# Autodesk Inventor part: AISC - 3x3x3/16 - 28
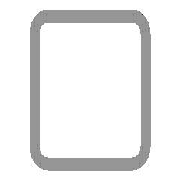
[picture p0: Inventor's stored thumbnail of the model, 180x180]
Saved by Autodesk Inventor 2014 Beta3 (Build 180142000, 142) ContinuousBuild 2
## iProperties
_CCFamilyMember: 9
_CCFamilyDisplayName: ANSI AISC (Square) - Tube
_FrameMemberDoc: Frame Member File
_Version: 15.0.0
_GetPNFromCC: 1
Created: 2010-11
Part Number: AISC - 3x3x3/16 - 28
Material: Steel, Mild
Description: Tube
Document SubType Name: Modeling
Standard: ANSI
Designer: Beta-8540w
Standards Organization: ANSI
Language: en-US
Size Designation: 3x3x3/16
Categories: <MemberInstance><Categories><Category DisplayName="Structural Shapes" InternalName="089c4875-fa83-4c05-b084-43b9cc11f5ed" Mnemonic="GRDR"><CategoryParameter Dis
Stock Number: 3x3x3/16
Density: 7.86 g/cm^3
Appearance: Steel
IsCustomPart: 1
G_L: 28.000 in
G_W: 3.000 in
G_H: 3.000 in
Author: Beta-8540w
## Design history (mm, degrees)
node "Start plane"
node "End plane"
sketch "Sketch"
  geometry: L1 (-38.1, -28.575)-(-38.1, 28.575); L2 (-28.575, 38.1)-(28.575, 38.1); L3 (38.1, 28.575)-(38.1, -28.575); L4 (28.575, -38.1)-(-28.575, -38.1); L5 (-28.575, 33.337)-(28.575, 33.338); L6 (33.338, 28.575)-(33.338, -28.575); L7 (28.575, -33.337)-(-28.575, -33.338); L8 (-33.338, -28.575)-(-33.338, 28.575); L9 (0, 56.102)-(0, -56.102) reference; L10 (-56.102, 0)-(56.102, 0) reference; A1 r 9.525 centre (-28.575, -28.575) between (-38.1, -28.575) and (-28.575, -38.1); A2 r 9.525 centre (-28.575, 28.575) between (-28.575, 38.1) and (-38.1, 28.575); A3 r 9.525 centre (28.575, 28.575) between (38.1, 28.575) and (28.575, 38.1); A4 r 9.525 centre (28.575, -28.575) between (28.575, -38.1) and (38.1, -28.575); A5 r 4.763 centre (-28.575, 28.575) between (-28.575, 33.337) and (-33.338, 28.575); A6 r 4.763 centre (28.575, 28.575) between (33.338, 28.575) and (28.575, 33.338); A7 r 4.763 centre (28.575, -28.575) between (28.575, -33.337) and (33.338, -28.575); A8 r 4.763 centre (-28.575, -28.575) between (-33.338, -28.575) and (-28.575, -33.338)
  constraints: 16 end point, 16 point on circle, 8 centre point, 8 tangent, 4 parallel, 3 equal radius, 2 perpendicular, 7 other
  dimensions: "d10" = 76.2 distance between parallel lines of L2 L4 (= G_H); "d11" = 76.2 distance between parallel lines of L1 L3 (= G_W); "d12" = 4.7625 distance between parallel lines of L3 L6 (= G_T); "d15" = 38.1 distance between parallel lines of L2 L10 (= 0.5 x d10); "d16" = 38.1 distance between parallel lines of L9 L3 (= 0.5 x d11); "d17" = 9.525 radius of A1 (= G_IR)
extrude "Body" new body sketch "Sketch" stored distance "d3" = 711.2 (= G_L); taper "d4" = 0 deg
node "Driven Length"
  sketch "Sketch3"
    geometry: L1 (0, 0)-(10, 0) reference
    constraints: 2 end point, 1 horizontal
  workplane "Work Plane3"
  sketch "Sketch4"
    geometry: L1 (-2, 0)-(12, 0) reference; L2 (-2, 711.2)-(12, 711.2) reference
    dimensions: "d19" = 711.2 distance between parallel lines of L1 L2 (derived)
body "Solid1"
other parameters: "G_W" = 76.2 [user parameter; used in 1 equation term], "G_H" = 76.2 [user parameter; used in 1 equation term], "G_T" = 4.7625 [user parameter; used in 1 equation term], "G_IR" = 9.525 [user parameter; used in 1 equation term], "G_L" = 711.2 (= d19) [user parameter; used in 1 equation term], "G_OFFSET_START" = 0 [user parameter; used in 1 equation term], "G_OFFSET_END" = 0 [user parameter; used in 1 equation term], "d13" = 0 (computed from G_OFFSET_START), "d14" = 711.2 (= G_OFFSET_END + B_L), "B_L" = 711.2 [user parameter; used in 1 equation term], "d18" = 90 deg
